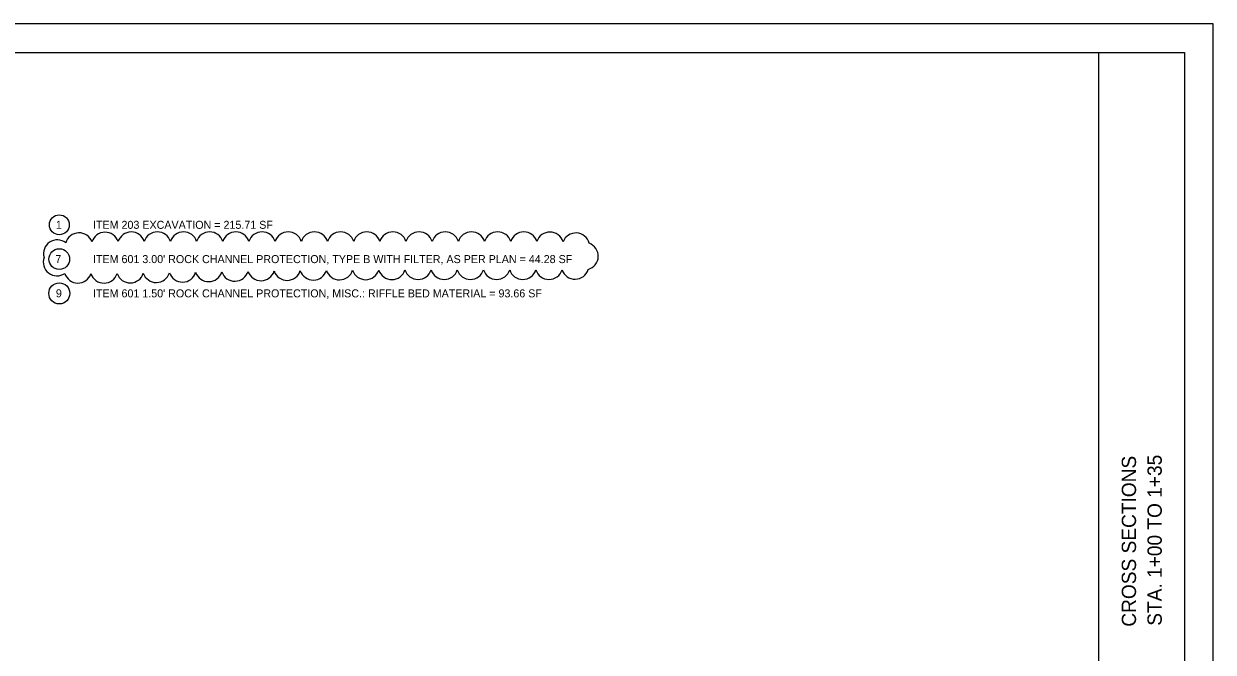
# Model space of a CAD drawing. Extents: x -149 to 57, y 0 to 22.
# Drawn here: x 13.19 to 34, y 11 to 22 of the extents above; entities that cross this region are included whole.
import ezdxf

# ---------------------------------------------------------------- set-up
doc = ezdxf.new("R2010")
doc.units = 0
for name, color, linetype in [('CS-ALGN-TEXT', 7, 'Continuous'), ('CS-ANNO', 7, 'Continuous'), ('CS-ANNO-MATC', 7, 'Continuous'), ('CS-ANNO-MATC-TEXT', 7, 'Continuous')]:
    doc.layers.add(name, color=color, linetype=linetype)

msp = doc.modelspace()

# ---------------------------------------------------------------- linework, layer by layer
at = {"layer": 'CS-ANNO'}
msp.add_lwpolyline([(0, 0), (34, 0), (34, 22), (0, 22)], close=True, dxfattribs=at)
at = {"layer": 'CS-ANNO-MATC'}
msp.add_line((32, 0.5), (32, 21.5), dxfattribs=at)
msp.add_lwpolyline([(1.5, 21.5), (33.5, 21.5), (33.5, 0.5), (1.5, 0.5)], close=True, dxfattribs=at)
at = {"layer": 'CS-ANNO-MATC-TEXT'}
for centre, radius in [((13.813, 18.481), 0.174), ((13.813, 17.881), 0.181), ((13.813, 17.281), 0.184)]:
    msp.add_circle(centre, radius, dxfattribs=at)
for centre, start, end in [((14.158, 18.101), 19.512, 164.512), ((14.614, 18.112), 18.2034, 163.2034), ((15.071, 18.116), 17.6965, 162.6965), ((15.529, 18.117), 17.5015, 162.5015), ((15.987, 18.117), 17.5, 162.5), ((16.444, 18.117), 17.5, 162.5), ((16.902, 18.117), 17.5, 162.5), ((17.36, 18.117), 17.5, 162.5), ((17.818, 18.117), 17.5, 162.5), ((18.276, 18.117), 17.5, 162.5), ((18.734, 18.117), 17.5, 162.5), ((19.192, 18.117), 17.5, 162.5), ((19.649, 18.117), 17.5, 162.5), ((20.107, 18.117), 17.5, 162.5), ((20.565, 18.117), 17.5, 162.5), ((21.023, 18.117), 17.5, 162.5), ((21.481, 18.117), 17.5, 162.5), ((21.939, 18.117), 17.5, 162.5), ((22.396, 18.115), 17.0766, 162.0766), ((22.85, 18.099), 14.0093, 159.0093), ((13.777, 17.978), 51.3115, 196.3115), ((23.002, 17.932), 285.3873, 70.3873), ((13.772, 17.828), 159.939, 304.939), ((18.715, 17.758), 197.9783, 342.9783), ((19.173, 17.761), 197.8509, 342.8509), ((19.631, 17.763), 197.7264, 342.7264), ((20.089, 17.765), 197.6048, 342.6048), ((20.547, 17.765), 197.5085, 342.5085), ((21.005, 17.765), 197.5, 342.5), ((21.463, 17.765), 197.5, 342.5), ((21.921, 17.765), 197.5, 342.5), ((22.379, 17.765), 197.5, 342.5), ((22.836, 17.769), 198.444, 343.444), ((14.139, 17.701), 196.7998, 341.7998), ((14.595, 17.7), 197.9033, 342.9033), ((15.053, 17.704), 198.2121, 343.2121), ((15.51, 17.711), 198.3635, 343.3635), ((15.968, 17.718), 198.4581, 343.4581), ((16.426, 17.726), 198.5244, 343.5244), ((16.884, 17.734), 198.5164, 343.5164), ((17.342, 17.742), 198.38, 343.38), ((17.799, 17.748), 198.2428, 343.2428), ((18.257, 17.753), 198.1089, 343.1089)]:
    msp.add_arc(centre, 0.24, start, end, dxfattribs=at)

# ---------------------------------------------------------------- texts
at = {"layer": 'CS-ALGN-TEXT'}
for s, p in [('CROSS SECTIONS', (32.65, 11.447)), ('STA. 1+00 TO 1+35', (33.1, 11.464))]:
    msp.add_text(s, height=0.25, rotation=90, dxfattribs=at).set_placement(p)
at = {"layer": 'CS-ANNO-MATC-TEXT'}
for s, p in [('1', (13.752, 18.411)), ('ITEM 203 EXCAVATION = 215.71 SF', (14.402, 18.411)), ('7', (13.743, 17.812)), ("ITEM 601 3.00' ROCK CHANNEL PROTECTION, TYPE B WITH FILTER, AS PER PLAN = 44.28 SF", (14.402, 17.811)), ('9', (13.753, 17.212)), ("ITEM 601 1.50' ROCK CHANNEL PROTECTION, MISC.: RIFFLE BED MATERIAL = 93.66 SF", (14.402, 17.211))]:
    msp.add_text(s, height=0.14, dxfattribs=at).set_placement(p)

doc.saveas('drawing.dxf')
